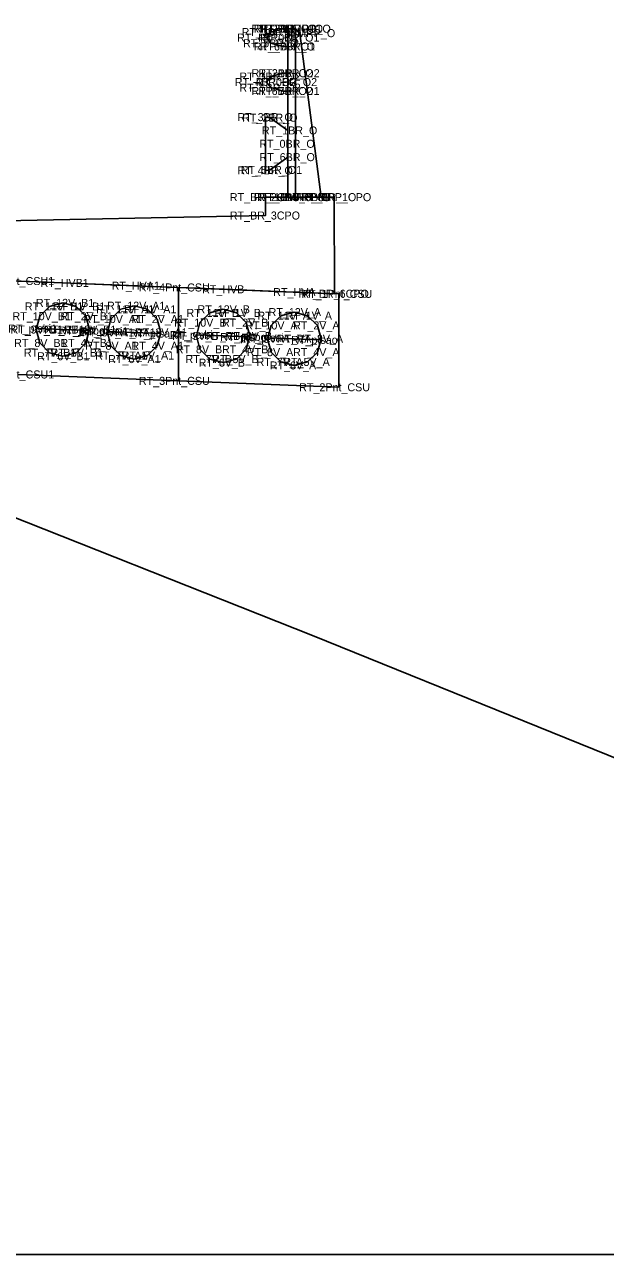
# Model space of a CAD drawing. Extents: x -26 to 1163, y -10 to 9537.
# Drawn here: x 99.37 to 110.24, y 5500 to 5523.04 of the extents above; entities that cross this region are included whole.
import ezdxf

# ---------------------------------------------------------------- set-up
doc = ezdxf.new("R2010")
doc.units = 0
for name, color, linetype in [('Exist Cross Section Cell', 7, 'Continuous'), ('Exist XS Ground Line', 7, 'Continuous'), ('Prop CMT Bridge Metal Rail', 7, 'Continuous'), ('Prop CMT Bridge Metal Rail Post', 7, 'Continuous'), ('Prop CMT Concrete Structures', 7, 'Continuous'), ('Prop CMT Corridor Surface Symbology Blue', 7, 'Continuous'), ('Scratch_Level_0', 7, 'Continuous')]:
    doc.layers.add(name, color=color, linetype=linetype)

msp = doc.modelspace()

# ---------------------------------------------------------------- linework, layer by layer
at = {"layer": 'Exist Cross Section Cell'}
msp.add_line((80, 5500), (160, 5500), dxfattribs=at)
at = {"layer": 'Exist XS Ground Line'}
msp.add_lwpolyline([(50.408, 5507.818), (57.975, 5511.563), (61.745, 5513.361), (70.287, 5515.157), (70.652, 5515.222), (76.125, 5515.292), (80, 5515.342), (82.665, 5515.377), (85.409, 5515.26), (94.805, 5514.85), (98.043, 5514.258), (104.757, 5511.598), (113.21, 5508.172), (121.817, 5507.493), (125.269, 5507.214), (127.758, 5507.11), (137.804, 5508.533), (143.24, 5508.791), (148.098, 5507.061), (150.039, 5505.923), (155.893, 5501.246), (156.599, 5500.79), (160, 5500.863)], dxfattribs=at)
at = {"layer": 'Prop CMT Bridge Metal Rail'}
for points in [[(104.293, 5522.965), (104.209, 5522.965), (103.98, 5522.902), (103.897, 5522.798)], [(103.897, 5522.798), (103.98, 5522.694), (104.209, 5522.632), (104.293, 5522.632)], [(104.293, 5522.798), (104.293, 5522.965)], [(104.293, 5522.632), (104.293, 5522.798)], [(104.293, 5522.132), (104.209, 5522.132), (103.98, 5522.069), (103.897, 5521.965)], [(104.293, 5521.965), (104.293, 5522.132)], [(103.897, 5521.965), (103.98, 5521.861), (104.209, 5521.798), (104.293, 5521.798)], [(104.293, 5521.798), (104.293, 5521.965)], [(104.293, 5521.059), (103.964, 5521.298), (103.876, 5521.309)], [(103.876, 5521.309), (103.876, 5520.309)], [(104.293, 5520.809), (104.293, 5521.059)], [(104.293, 5520.559), (104.293, 5520.809)], [(103.876, 5520.309), (103.964, 5520.319), (104.293, 5520.559)]]:
    msp.add_lwpolyline(points, dxfattribs=at)
at = {"layer": 'Prop CMT Bridge Metal Rail Post'}
for points in [[(104.293, 5519.809), (104.293, 5522.965)], [(104.293, 5522.965), (104.438, 5522.965)], [(104.438, 5522.965), (104.438, 5519.809)], [(104.438, 5522.965), (104.522, 5522.882), (104.918, 5519.809)]]:
    msp.add_lwpolyline(points, dxfattribs=at)
at = {"layer": 'Prop CMT Concrete Structures'}
for points in [[(98.375, 5518.272), (98.376, 5519.355), (103.875, 5519.465), (103.876, 5519.809), (105.166, 5519.809), (105.167, 5518)], [(105.167, 5518), (98.375, 5518.272)], [(99.25, 5518.237), (100.083, 5518.203), (101.417, 5518.15), (102.25, 5518.117)], [(102.25, 5518.117), (102.25, 5516.367)], [(102.25, 5518.117), (103.083, 5518.083), (104.417, 5518.03), (105.25, 5517.997)], [(102.25, 5516.367), (102.25, 5518.117)], [(105.25, 5517.997), (105.25, 5516.247)], [(99.583, 5517.328), (99.65, 5517.578), (99.833, 5517.761), (100.083, 5517.828)], [(100.083, 5517.828), (100.333, 5517.761), (100.516, 5517.578), (100.583, 5517.328)], [(100.917, 5517.275), (100.984, 5517.525), (101.167, 5517.708), (101.417, 5517.775)], [(101.417, 5517.775), (101.667, 5517.708), (101.85, 5517.525), (101.917, 5517.275)], [(102.583, 5517.208), (102.65, 5517.458), (102.833, 5517.641), (103.083, 5517.708)], [(103.083, 5517.708), (103.333, 5517.641), (103.516, 5517.458), (103.583, 5517.208)], [(103.917, 5517.155), (103.984, 5517.405), (104.167, 5517.588), (104.417, 5517.655)], [(104.417, 5517.655), (104.667, 5517.588), (104.85, 5517.405), (104.917, 5517.155)], [(100.583, 5517.328), (100.516, 5517.078), (100.333, 5516.895), (100.083, 5516.828), (99.833, 5516.895), (99.65, 5517.078), (99.583, 5517.328)], [(101.917, 5517.275), (101.85, 5517.025), (101.667, 5516.842), (101.417, 5516.775), (101.167, 5516.842), (100.984, 5517.025), (100.917, 5517.275)], [(103.583, 5517.208), (103.516, 5516.958), (103.333, 5516.775), (103.083, 5516.708), (102.833, 5516.775), (102.65, 5516.958), (102.583, 5517.208)], [(104.917, 5517.155), (104.85, 5516.905), (104.667, 5516.722), (104.417, 5516.655), (104.167, 5516.722), (103.984, 5516.905), (103.917, 5517.155)], [(102.25, 5516.367), (99.25, 5516.487)], [(105.25, 5516.247), (102.25, 5516.367)]]:
    msp.add_lwpolyline(points, dxfattribs=at)
at = {"layer": 'Prop CMT Corridor Surface Symbology Blue'}
for points in [[(99.593, 5517.348), (100.083, 5517.328), (100.573, 5517.309)], [(100.927, 5517.295), (101.417, 5517.275), (101.907, 5517.255)], [(102.593, 5517.228), (103.083, 5517.208), (103.573, 5517.189)], [(103.927, 5517.175), (104.417, 5517.155), (104.907, 5517.135)]]:
    msp.add_lwpolyline(points, dxfattribs=at)

# ---------------------------------------------------------------- texts
at = {"layer": 'Scratch_Level_0'}
for s, p in [('RT_2BMRP_O', (103.617, 5522.89)), ('RT_2BR_O1', (103.66, 5522.89)), ('RT_3BMRP_O', (103.763, 5522.89)), ('RT_1BR_O1', (103.786, 5522.89)), ('RT_4BR_O1', (103.348, 5522.723)), ('RT_3BR_O1', (103.431, 5522.827)), ('RT_5BR_O', (103.456, 5522.619)), ('RT_0BR_O1', (103.738, 5522.723)), ('RT_5BMRP_O', (103.846, 5522.807)), ('RT_6BR_O1', (103.657, 5522.557)), ('RT_7BR_O', (103.768, 5522.557)), ('RT_3BR_O2', (103.388, 5521.994)), ('RT_2BR_O2', (103.618, 5522.057)), ('RT_1BR_O2', (103.743, 5522.057)), ('RT_4BR_O2', (103.305, 5521.89)), ('RT_5BR_O2', (103.388, 5521.786)), ('RT_6BR_O2', (103.614, 5521.723)), ('RT_0BR_O2', (103.695, 5521.89)), ('RT_7BR_O1', (103.743, 5521.723)), ('RT_3BR_O', (103.352, 5521.234)), ('RT_2BR_O', (103.44, 5521.223)), ('RT_1BR_O', (103.811, 5520.984)), ('RT_0BR_O', (103.762, 5520.734)), ('RT_6BR_O', (103.765, 5520.484)), ('RT_4BR_O', (103.352, 5520.234)), ('RT_5BR_O1', (103.415, 5520.244)), ('RT_BR_2CPO', (103.21, 5519.734)), ('RT_1BMRP_O', (103.66, 5519.734)), ('RT_4BMRP_O', (103.763, 5519.734)), ('RT_6BMRP_O', (104.239, 5519.734)), ('RT_BR_1CPO', (104.542, 5519.734)), ('RT_BR_3CPO', (103.209, 5519.39)), ('RT_4Pnt_CSU1', (98.483, 5518.162)), ('RT_HVB1', (99.666, 5518.128)), ('RT_HVA1', (100.997, 5518.075)), ('RT_4Pnt_CSU', (101.508, 5518.042)), ('RT_HVB', (102.691, 5518.008)), ('RT_HVA', (104.022, 5517.955)), ('RT_BR_6CPO', (104.497, 5517.925)), ('RT_1Pnt_CSU', (104.551, 5517.922)), ('RT_11V_B1', (99.373, 5517.686)), ('RT_12V_B1', (99.58, 5517.753)), ('RT_1V_B1', (99.898, 5517.686)), ('RT_11V_A1', (100.704, 5517.633)), ('RT_12V_A1', (100.911, 5517.7)), ('RT_1V_A1', (101.228, 5517.633)), ('RT_11V_B', (102.398, 5517.566)), ('RT_12V_B', (102.605, 5517.633)), ('RT_1V_B', (102.922, 5517.566)), ('RT_12V_A', (103.936, 5517.58)), ('RT_10V_B1', (99.141, 5517.503)), ('RT_2V_B1', (100.038, 5517.503)), ('RT_10V_A1', (100.472, 5517.45)), ('RT_2V_A1', (101.369, 5517.45)), ('RT_10V_B', (102.166, 5517.383)), ('RT_2V_B', (103.063, 5517.383)), ('RT_10V_A', (103.497, 5517.33)), ('RT_11V_A', (103.728, 5517.513)), ('RT_1V_A', (104.253, 5517.513)), ('RT_2V_A', (104.394, 5517.33)), ('RT_ptsbi1', (99.062, 5517.273)), ('RT_9V_B1', (99.105, 5517.253)), ('RT_VB1', (99.734, 5517.253)), ('RT_ptsbo1', (100.002, 5517.234)), ('RT_3V_B1', (100.105, 5517.253)), ('RT_ptsai1', (100.394, 5517.22)), ('RT_9V_A1', (100.436, 5517.2)), ('RT_VA1', (101.065, 5517.2)), ('RT_ptsao1', (101.334, 5517.18)), ('RT_3V_A1', (101.436, 5517.2)), ('RT_ptsbi', (102.087, 5517.153)), ('RT_9V_B', (102.13, 5517.133)), ('RT_VB', (102.759, 5517.133)), ('RT_ptsbo', (103.026, 5517.114)), ('RT_3V_B', (103.13, 5517.133)), ('RT_ptsai', (103.419, 5517.1)), ('RT_9V_A', (103.461, 5517.08)), ('RT_VA', (104.09, 5517.08)), ('RT_3V_A', (104.461, 5517.08)), ('RT_8V_B1', (99.172, 5517.003)), ('RT_4V_B1', (100.038, 5517.003)), ('RT_8V_A1', (100.503, 5516.95)), ('RT_4V_A1', (101.369, 5516.95)), ('RT_8V_B', (102.197, 5516.883)), ('RT_4V_B', (103.063, 5516.883)), ('RT_ptsao', (104.359, 5517.06)), ('RT_7V_B1', (99.355, 5516.82)), ('RT_6V_B1', (99.601, 5516.753)), ('RT_5V_B1', (99.855, 5516.82)), ('RT_7V_A1', (100.686, 5516.767)), ('RT_6V_A1', (100.932, 5516.7)), ('RT_5V_A1', (101.186, 5516.767)), ('RT_7V_B', (102.38, 5516.7)), ('RT_6V_B', (102.626, 5516.633)), ('RT_5V_B', (102.88, 5516.7)), ('RT_8V_A', (103.528, 5516.83)), ('RT_7V_A', (103.711, 5516.647)), ('RT_5V_A', (104.211, 5516.647)), ('RT_4V_A', (104.394, 5516.83)), ('RT_3Pnt_CSU1', (98.483, 5516.412)), ('RT_6V_A', (103.957, 5516.58)), ('RT_3Pnt_CSU', (101.508, 5516.292)), ('RT_2Pnt_CSU', (104.508, 5516.172))]:
    msp.add_text(s, height=0.15, dxfattribs=at).set_placement(p)

doc.saveas('drawing.dxf')
